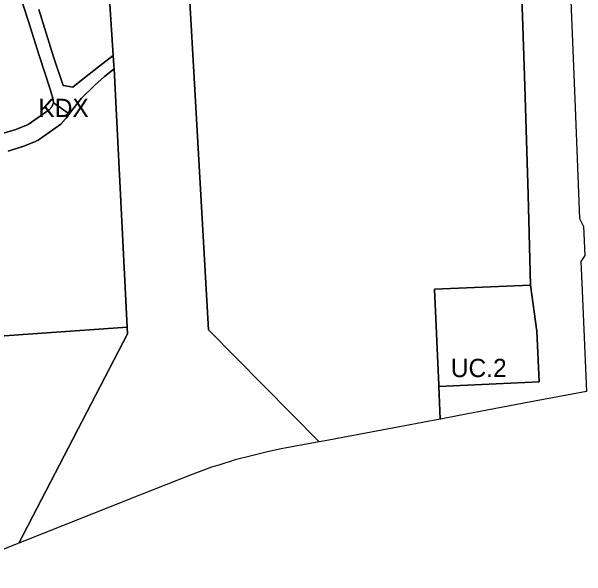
# Model space of a CAD drawing. Extents: x 7431767 to 7433133, y 5549450 to 5550702.
# Drawn here: x 7432818.5 to 7433132.5, y 5549584.1 to 5549892.8 of the extents above; entities that cross this region are included whole.
import ezdxf

# ---------------------------------------------------------------- set-up
doc = ezdxf.new("R2010")
doc.units = 0
doc.layers.add('linie_rozgraniczajace', color=7, linetype='Continuous')
doc.layers.add('oznaczenia_przeznaczen', color=7, linetype='Continuous')

msp = doc.modelspace()

# ---------------------------------------------------------------- linework, layer by layer
at = {"layer": 'linie_rozgraniczajace'}
for points in [[(7432902.03, 5550144.07), (7432944.13, 5550145.61), (7432981.56, 5550147.13), (7433003.98, 5550148.04), (7433031.05, 5550149.14), (7433038.87, 5549969.61), (7433065.04, 5549974.28), (7433094.13, 5549980.23), (7433096.9, 5549912.02), (7433098.83, 5549852.15), (7433100.71, 5549792.71), (7433102, 5549743.28), (7433049.61, 5549741.16), (7433051.89, 5549688.75), (7433051.92, 5549688.03), (7433052.68, 5549670.09), (7433033.34, 5549666.48), (7432989.73, 5549658.32), (7432986.51, 5549657.72), (7432926.04, 5549718.82), (7432902.17, 5550141.56)], [(7433051.92, 5549688.03), (7433051.89, 5549688.75), (7433049.61, 5549741.16), (7433102, 5549743.28), (7433105.4, 5549718.13), (7433106.64, 5549690.55)]]:
    msp.add_lwpolyline(points, close=True, dxfattribs=at)
for points in [[(7432902.17, 5550141.56), (7432926.04, 5549718.82), (7432986.51, 5549657.72), (7432965.77, 5549653.85), (7432958.24, 5549652.26), (7432949.63, 5549650.11), (7432940.72, 5549647.83), (7432931.7, 5549645.05), (7432929.01, 5549644.2), (7432927.68, 5549643.78), (7432915.73, 5549639.32), (7432889.91, 5549629.1), (7432822.5, 5549602.39), (7432881.85, 5549716.68), (7432881.66, 5549720.43), (7432874.56, 5549861.59), (7432874.46, 5549863.38), (7432874.08, 5549868.83), (7432869.08, 5549944.9)], [(7432869.08, 5549944.9), (7432874.08, 5549868.83), (7432866.05, 5549862.56), (7432860.92, 5549858.57), (7432855.02, 5549853.82), (7432851.99, 5549851.44), (7432848.05, 5549852.19), (7432846.66, 5549852.46), (7432841.52, 5549868.15), (7432833.47, 5549893.91)], [(7433122.71, 5549930.24), (7433126.27, 5549840.32), (7433128.67, 5549779.68), (7433130.94, 5549775.43), (7433131.61, 5549759.6), (7433129.46, 5549756.31), (7433129.97, 5549744.42), (7433132.53, 5549685.26), (7433098.27, 5549678.76), (7433066.74, 5549672.76), (7433056.5, 5549670.8), (7433053.05, 5549670.16), (7433052.68, 5549670.09), (7433051.92, 5549688.03), (7433106.64, 5549690.55), (7433105.4, 5549718.13), (7433102, 5549743.28), (7433100.71, 5549792.71), (7433098.83, 5549852.15), (7433096.9, 5549912.02)], [(7432821.48, 5549907.18), (7432827.79, 5549887.38), (7432833.7, 5549868.85), (7432839.64, 5549850.46), (7432841.34, 5549844.78), (7432841.42, 5549842.93), (7432840.53, 5549840.81), (7432839.1, 5549839.13), (7432827.7, 5549831.06), (7432820.96, 5549828.3), (7432814.2, 5549826.27)], [(7432833.47, 5549893.91), (7432841.52, 5549868.15), (7432846.66, 5549852.46), (7432848.05, 5549852.19), (7432851.99, 5549851.44), (7432855.02, 5549853.82), (7432860.92, 5549858.57), (7432866.05, 5549862.56), (7432874.08, 5549868.83), (7432874.46, 5549863.38), (7432874.56, 5549861.59), (7432869.26, 5549857.25), (7432863.77, 5549852.38), (7432856.79, 5549845.47), (7432850.01, 5549836.97), (7432841.42, 5549842.93), (7432841.34, 5549844.78), (7432839.64, 5549850.46), (7432833.7, 5549868.85), (7432827.79, 5549887.38), (7432821.48, 5549907.18)], [(7432816.75, 5549816.59), (7432824.07, 5549818.8), (7432824.44, 5549818.94), (7432832.01, 5549822.01), (7432832.22, 5549822.1), (7432833.02, 5549822.57), (7432845.39, 5549831.33), (7432846.18, 5549832.02), (7432846.26, 5549832.15), (7432848.38, 5549834.62), (7432849.1, 5549835.44), (7432850.01, 5549836.97), (7432856.79, 5549845.47), (7432863.77, 5549852.38), (7432869.26, 5549857.25), (7432874.56, 5549861.59), (7432881.66, 5549720.43), (7432801.62, 5549714.66)], [(7432814.2, 5549826.27), (7432820.96, 5549828.3), (7432827.7, 5549831.06), (7432839.1, 5549839.13), (7432840.53, 5549840.81), (7432841.42, 5549842.93), (7432850.01, 5549836.97), (7432849.1, 5549835.44), (7432848.38, 5549834.62), (7432846.26, 5549832.15), (7432846.18, 5549832.02), (7432845.39, 5549831.33), (7432833.02, 5549822.57), (7432832.22, 5549822.1), (7432832.01, 5549822.01), (7432824.44, 5549818.94), (7432824.07, 5549818.8), (7432816.75, 5549816.59)], [(7432801.62, 5549714.66), (7432881.66, 5549720.43), (7432881.85, 5549716.68), (7432822.5, 5549602.39), (7432776.42, 5549584.13)]]:
    msp.add_lwpolyline(points, dxfattribs=at)

# ---------------------------------------------------------------- texts
at = {"layer": 'oznaczenia_przeznaczen'}
for s, p in [('KDX', (7432833.22, 5549835.15)), ('UC.2', (7433058.45, 5549693.07))]:
    msp.add_text(s, height=10, dxfattribs=at).set_placement(p)

doc.saveas('drawing.dxf')
